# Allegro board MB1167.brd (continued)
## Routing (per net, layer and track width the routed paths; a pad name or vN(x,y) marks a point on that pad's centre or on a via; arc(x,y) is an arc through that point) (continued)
U5V_ST_LINK: length 36.3
  TOP w0.508: 35.83,58.04 C55.2 35.18,57.43 ; 36.22,57.53 U17.6 ; U17.7 34.95,57.02
  BOTTOM w1.016: 35.48,60.91 5.38,60.91 4.57,61.72 JP13.11
  vias: v1(36.2,60.07) v1(36.2,59.44)
USB_RENUMN: length 11
  TOP w0.127: U21.38 30.44,35.9 29.72,35.18 24.26,35.18 v1(22.35,33.27)
  BOTTOM w0.127: R294.2 v1(22.35,33.27)
VREF+: length 16.3
  TOP w0.381: v5(73.21,143.29) 73.61,142.89 U4.P1
  TOP w0.508: R33.2 v1(67.94,145.54)
  BOTTOM w0.381: C110.2 73.66,143.76 73.21,143.31 v5(73.21,143.29)
  BOTTOM w0.508: v5(73.21,143.29) 72.87,143.29 72.26,143.89 69.72,143.89 68.07,145.54 v1(67.94,145.54) 67.18,146.3 C105.1 66.55,149.22 67.18,149.86 TP6.1
VUSB_ST_LINK: length 77.1
  TOP w0.508: 30.78,50.16 C59.1 ; C59.1 32.72,50.16 ; C59.1 31.75,51 ; C59.1 31.75,49.33 ; U17.1 33.68,51.68 ; U17.1 34.16,50.59 ; U17.1 33.2,50.59 ; U17.1 33.68,49.5 ; 31.88,51.85 R156.1 ; R156.1 31.27,52.45 ; R156.1 32.49,52.45 ; R200.1 11.68,21.59 CN21.1 ; 34.95,49.5 U17.2 ; U17.2 34.47,50.59 ; U17.2 34.95,51.94 ; 26.2,74.93 D12.1 ; D12.1 26.82,75.54 ; D12.1 26.82,74.32 ; R159.1 35.2,49.07 ; R159.1 34.72,48.59 ; R159.1 35.2,48.11
  L4_SIG w1.016: 28.83,56.39 28.83,60.83 25.4,64.26 25.4,71.96 25.81,72.36 ; 28.83,52.73 28.83,45.87 18.24,35.28 18.24,33.81
  BOTTOM w0.508: 17.82,33.15 R293.2 18.41,33.76
  BOTTOM w1.016: CN21.1 14.35,24.26 14.35,31.75 15.95,33.35 16.51,33.35
  vias: v1(17.35,33.73) v1(17.37,33.02) v1(26.04,73.91) v1(26.67,73.91) v1(28.8,55.37) v1(28.8,54.66) v1(28.8,53.9)

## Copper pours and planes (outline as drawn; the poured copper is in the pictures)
+1V8 on TOP: 107.06,43.05 108.46,43.05 108.97,43.56 108.97,47.62 109.22,47.88 110.49,47.88 110.87,47.5 110.87,43.56 111.38,43.05 119.51,43.05 120.14,42.42 120.14,38.35 119.63,37.85 108.36,37.85 106.68,39.52 106.68,42.67
+1V8 on BOTTOM: 154.56,159.38 154.81,159.13 154.81,156.72 154.56,156.46 148.13,156.46 147.32,155.65 147.32,119.13 139.01,110.82 139.01,100.3 138.53,99.82 136.4,99.82 136.02,100.2 136.02,111.46 143.89,119.33 143.89,153.85 143.76,153.97 143.76,158.37 144.78,159.38
+1V8 on BOTTOM: 115.7,42.67 120.52,42.67 121.28,41.91 121.28,27.64 119.05,25.4 115.82,25.4 114.94,26.29 114.94,41.91
+1V8 on L4_SIG: 134.75,101.47 137.79,101.47 138.3,100.97 138.3,100.08 136.27,98.04 135.51,98.04 131.95,94.49 131.95,92.08 123.06,83.19 123.06,40.89 120.14,37.97 116.08,37.97 115.82,38.23 115.82,42.67 116.71,43.56 117.98,43.56 119.25,44.83 119.25,85.98
+2V8 on TOP: 140.08,156.59 140.46,156.21 140.46,151 140.21,150.75 131.06,150.75 130.43,151.38 130.43,155.32 131.83,156.72 131.83,160.53 131.95,160.66 133.6,160.66 133.73,160.53 133.73,157.23 134.37,156.59
+2V8 on L3_VCC: 136.76,137.16 134.87,139.04 134.87,156.1 137.27,158.5 156.34,158.5 156.34,148.34 156.34,148.33 156.34,146.18 156.21,146.05 153.03,146.05 152.15,145.16 152.15,137.77 151.53,137.16
+3V3 on TOP: 43.31,56.13 61.21,56.13 61.59,55.75 61.59,52.45 60.96,51.82 56.26,51.82 55.75,51.31 55.75,44.2 55.24,43.69 43.56,43.69 42.55,44.7 42.55,55.37
+3V3 on TOP: 106.3,48.51 108.2,48.51 108.46,48.26 108.46,44.7 108.2,44.45 106.3,44.45 106.05,44.7 106.05,48.26
+3V3 on L3_VCC: 0.51,0.51 0.51,13.93 29.55,13.93 31.33,15.72 31.33,26.01 31.97,26.65 40.54,26.65 42.5,28.61 42.5,40.06 41.02,41.54 26.76,41.54 24.07,44.24 24.07,69.76 22.46,71.36 0.51,71.36 0.51,82.03 2,82.03 2.39,82.43 2.39,83.5 2,83.9 0.51,83.9 0.51,86.78 2,86.78 2.39,87.18 2.39,88.25 2,88.65 0.51,88.65 0.51,96.39 2,96.39 2.39,96.78 2.39,97.86 2,98.25 0.51,98.25 0.51,101.14 2,101.14 2.39,101.53 2.39,102.61 2,103 0.51,103 0.51,106.93 5.95,106.93 6.6,107.59 6.6,111.1 5.95,111.76 3.41,111.76 3.3,111.87 3.3,113.69 3.41,113.79 5.19,113.79 6.35,114.96 6.35,116.1 6.96,116.71 7.34,116.71 8,117.37 8,118.85 7.6,119.25 0.51,119.25 0.51,172.21 156.34,172.21 156.34,159 137.05,159 134.37,156.32 134.37,138.83 136.55,136.65 151.74,136.65 152.65,137.56 152.65,144.91 153.29,145.54 155.96,145.54 156.34,145.16 156.34,52.91 155.69,47.08 156.34,41.24 156.34,0.51 ; 1 cut-out
+3V3_ST_LINK on L3_VCC: 0.51,14.44 0.51,70.86 22.25,70.86 23.56,69.55 23.56,44.03 26.55,41.03 40.81,41.03 42,39.85 42,28.82 40.33,27.16 31.76,27.16 30.83,26.22 30.83,15.93 29.34,14.44
+5V on TOP: 11.07,63.17 9.47,61.57 6.58,61.57 6.02,62.13 6.02,76.35 6.54,76.87 13.32,76.87 13.77,76.43 13.77,71.04 16.55,68.26 48.2,68.26 48.64,67.82 48.64,62.61 47.88,61.85 47.88,56.9 47.62,56.64 43.81,56.64 43.43,57.02 43.43,62.48 42.75,63.17
+5V on TOP: 130.68,157.48 128.78,157.48 128.27,157.99 128.27,162.23 128.47,162.43 130.86,162.43 131.06,162.23 131.06,157.86
+5V on BOTTOM: 13.84,92.15 12.09,92.15 11.68,92.56 11.68,97.97 16.59,102.87 16.59,115.16 17.22,115.8 21.01,115.8 21.21,115.6 21.21,114.17 19.91,112.88 19.91,102.57 14.05,96.7 14.05,92.35
+5V on L4_SIG: 130.07,161.59 128.57,161.59 128.32,161.85 128.32,167.94 125.93,170.33 115.44,170.33 110.39,165.28 109.65,165.28 107.92,167 71.27,167 69.9,168.38 30.23,168.38 28.92,167.07 28.92,156.53 28.57,156.18 28.57,149.61 19.3,140.34 19.3,118.24 20.93,116.61 20.95,116.61 21.36,116.2 21.36,113.51 21.03,113.18 17.5,113.18 12.19,118.49 12.19,142.56 25.34,155.7 25.34,168.16 28.42,171.25 113.42,171.25 114.16,171.98 127.91,171.98 130.33,169.57 130.33,161.85
+5V on L4_SIG: 8.66,97.46 13.21,97.46 13.74,96.93 13.74,72.75 12.62,71.63 6.38,71.63 6.05,71.96 6.05,76.63 10.64,81.23 10.64,94.36 10.19,94.82 8.81,94.82 8.51,95.12 8.51,97.31
D5V on TOP: 39.67,125.68 39.67,123.88 37.97,122.17 29.34,122.17 28.96,122.56 28.96,123.44 29.21,123.7 36.96,123.7 39.12,125.86 39.5,125.86
D5V on TOP: 42.93,125.91 44.22,125.91 44.58,125.55 44.58,121.62 45.06,121.13 45.06,120.7 44.88,120.52 43.97,120.52 43.64,120.85 43.64,122.58 43.66,122.61 43.66,124.69 43.31,125.04 43.03,125.04 42.93,125.15
D5V on TOP: 106.93,125.98 108.08,125.98 108.2,125.86 108.2,124.97 108.08,124.84 106.93,124.84 106.81,124.97 106.81,125.86
D5V on BOTTOM: 14.68,95.22 15.21,95.22 21.54,101.55 21.54,112.12 22.89,113.46 22.89,116.71 28.47,122.3 30.48,122.3 30.73,122.56 30.73,123.32 30.35,123.7 27.69,123.7 21.84,117.86 21.84,113.92 20.42,112.5 20.42,102.06 14.43,96.06 14.43,95.48
D5V on L4_SIG: 106.93,125.98 108.33,125.98 108.58,125.73 108.58,124.59 105.92,121.92 97.16,121.92 95,119.76 62.36,119.76 60.55,121.56 47.88,121.56 46.58,120.27 44.07,120.27 43.94,120.4 43.94,121.54 44.2,121.79 45.82,121.79 46.58,122.56 61.21,122.56 62.74,121.03 94.11,121.03 96.14,123.06 104.9,123.06 106.81,124.97 106.81,125.86
D5V on L4_SIG: 14.71,96.47 15.6,96.47 15.82,96.24 15.82,72.01 10.36,66.55 3.84,66.55 3.4,66.98 3.4,68.99 3.73,69.32 8.36,69.32 8.56,69.11 10.97,69.11 14.58,72.72 14.58,96.34
GND on BOTTOM (solid shape): 35.31,29.56 35.81,30.06 35.81,28.7 34.8,28.7 34.8,30.07
GND on TOP: 22.86,117.86 33.4,117.86 34.92,116.33 34.92,113.41 32.89,111.38 30.48,111.38 30.48,112.78 26.8,112.78 26.8,111.38 25.53,111.38 25.34,111.19 25.34,109.41 25.15,109.22 22.35,109.22 21.97,109.6 21.97,116.97
GND on TOP: 77.6,151.38 69.47,151.38 69.22,151.64 69.22,155.45 71.75,157.99 91.57,157.99 91.95,157.61 91.95,150.75 91.03,149.83 87.02,149.83 85.72,151.13 77.85,151.13
GND on TOP: 111.89,48.51 118.75,48.51 119,48.26 119,44.32 118.62,43.94 111.89,43.94 111.63,44.2 111.63,48.26
GND on TOP: 141.48,156.34 143.64,156.34 144.15,155.83 144.15,151.38 143.64,150.88 141.22,150.88 140.97,151.13 140.97,155.83
GND on TOP: 22.23,59.31 27,59.31 27.46,58.85 27.46,52.35 27.18,52.07 22.1,52.07 21.72,52.45 21.72,58.8
GND on TOP: 54.48,56.9 54.23,56.64 50.55,56.64 50.36,56.83 50.36,61.28 50.16,61.47 50.16,67.31 50.42,67.56 61.09,67.56 61.59,67.06 61.59,57.15 61.34,56.9
GND on TOP: 43.94,20.32 42.49,18.87 27.89,18.87 27.84,18.92 16.97,18.92 15.7,20.19 15.7,26.92 18.21,29.44 19.53,29.44 23.06,32.97 27.64,32.97 28.31,32.3 28.31,28.63 30.85,26.09 43.38,26.09 43.94,25.53
GND on TOP: 141.25,131.93 141.4,132.08 144.17,132.08 144.53,131.72 144.53,117.35 144.27,117.09 137.79,117.09 137.29,117.6 137.29,126.49 137.34,126.49 138.1,127.23 138.79,127.48 139.6,128.09 140,128.5 140.18,128.7 140.4,128.98 140.58,129.26 140.75,129.58 140.91,129.94 141.07,130.45 141.17,130.94 141.2,131.12
GND on BOTTOM: 29.18,25.98 41.86,25.98 42.82,25.02 42.82,19.86 42.19,19.23 28.96,19.23 28.5,19.68 28.5,25.3
GND on BOTTOM: 24.92,117.91 32.44,117.91 33.63,116.71 33.63,112.55 32.64,111.56 24.43,111.56 24.42,111.57 24.23,111.57 23.94,111.86 22.66,111.86 22.56,111.96 22.56,112.34 23.22,113 23.22,116.2
GND on L2_GND, L5_GND: 0.51,0.51 0.51,82.03 2,82.03 2.39,82.43 2.39,83.5 2,83.9 0.51,83.9 0.51,86.78 2,86.78 2.39,87.18 2.39,88.25 2,88.65 0.51,88.65 0.51,96.39 2,96.39 2.39,96.78 2.39,97.86 2,98.25 0.51,98.25 0.51,101.14 2,101.14 2.39,101.53 2.39,102.61 2,103 0.51,103 0.51,106.93 5.95,106.93 6.6,107.59 6.6,111.1 5.95,111.76 3.41,111.76 3.3,111.87 3.3,113.69 3.41,113.79 5.19,113.79 6.35,114.96 6.35,116.1 6.96,116.71 7.34,116.71 8,117.37 8,118.85 7.6,119.25 0.51,119.25 0.51,172.21 156.34,172.21 156.34,52.91 155.69,47.08 156.34,41.24 156.34,0.51
GND on L4_SIG: outline of 149 points within 0.56,0.64 156.34,117.6
GND on L4_SIG: 55.14,139.57 57.07,137.64 66.27,137.64 66.55,137.36 66.55,135.13 66.04,134.62 56.54,134.62 54.31,136.86 44.53,136.86 43.99,137.39 43.99,138.4 44.18,138.6 44.18,139.23 44.53,139.57
GND on L4_SIG: 41.15,106.3 48.39,106.3 49.91,104.78 49.91,82.17 65.28,66.8 91.95,66.8 93.6,65.15 93.6,61.98 89.62,58 87.72,58 85.75,56.03 85.75,54.13 76.23,44.6 75.13,44.6 73.23,42.7 56.82,42.7 55.52,41.4 51.69,41.4 48.11,37.82 34.29,37.82 33.77,38.34 33.77,61.35 29.72,65.41 29.72,93.42 39.5,103.2 39.5,104.65
GND on L4_SIG: 24.23,118.49 31.88,118.49 33.99,116.38 33.99,113.11 30.81,109.93 30.81,103.58 30.1,102.87 24.21,102.87 23.75,103.33 23.75,106.81 22.1,108.46 22.1,112.09 22.83,112.83 22.83,117.09
VBUS_FS2 on TOP (solid shape): 15.24,113.54 14.22,113.54 14.22,114.9 14.73,114.39 15.24,114.9
VDD_MCU on BOTTOM: 59.56,149.86 60.58,150.88 61.85,150.88 62.36,150.37 62.36,139.06 62.1,138.81 59.82,138.81 59.56,139.06
VDD_MCU on L3_VCC: 58.78,130.3 58.17,130.92 58.17,150.52 58.78,151.13 61.87,151.13 62.23,150.77 62.23,148.23 62.89,147.57 71.73,147.57 74.27,150.11 87.78,150.11 89.41,148.48 89.41,131.93 87.78,130.3
E5V on TOP: 20.83,52.7 20.83,58.8 20.32,59.31 7.11,59.31 5.72,60.71 5.72,65.79 5.21,66.29 1.27,66.29 1.02,66.04 1.02,54.74 1.4,54.36 12.19,54.36 14.29,52.26 20.38,52.26
MIC_CLK on BOTTOM (solid shape): 123.19,14.73 121.82,14.73 122.33,15.24 121.83,15.75 123.19,15.75
MIC_DATA on BOTTOM (solid shape): 129.67,14.73 128.75,14.73 128.24,15.24 128.75,15.75 129.67,15.75
NETC5_1 on TOP: 134.49,163.32 136.53,163.32 137.03,162.81 137.03,159.64 137.16,159.51 139.19,159.51 139.45,159.26 139.45,157.35 139.19,157.1 134.87,157.1 134.24,157.73 134.24,163.07
NETC6_2 on TOP (solid shape): 64.64,159.99 64.14,159.48 63.63,159.99 63.63,160.91 64.64,160.91
NETC6_2 on BOTTOM (solid shape): 40.86,145.79 41.37,145.29 40.01,145.29 40.01,146.3 41.37,146.3
NETC7_2 on TOP (solid shape): 70.99,160.12 70.48,159.61 69.98,160.12 69.98,161.04 70.99,161.04
NETC7_2 on BOTTOM (solid shape): 116.59,132.72 115.22,132.72 115.73,133.23 115.22,133.73 116.59,133.73
NETC8_2 on BOTTOM (solid shape): 48.13,150.24 46.77,150.24 47.28,150.75 46.77,151.26 48.13,151.26
NETC9_2 on BOTTOM (solid shape): 40.86,148.84 41.37,148.34 40.01,148.34 40.01,149.35 41.37,149.35
NETC10_2 on BOTTOM (solid shape): 109.57,130.81 110.07,130.3 108.71,130.3 108.71,131.32 110.08,131.32
NETC11_1 on BOTTOM (solid shape): 48.13,129.03 47.21,129.03 46.7,129.54 47.21,130.05 48.13,130.05
NETC12_2 on BOTTOM (solid shape): 48.13,137.29 47.21,137.29 46.7,137.79 47.21,138.3 48.13,138.3
NETC13_2 on BOTTOM (solid shape): 41.43,141.6 40.93,141.1 40.01,141.1 40.01,142.11 40.93,142.11
NETC14_2 on BOTTOM (solid shape): 48.13,147.07 47.21,147.07 46.7,147.57 47.21,148.08 48.13,148.08
NETC15_1 on BOTTOM (solid shape): 41.43,139.83 40.93,139.32 40.01,139.32 40.01,140.34 40.93,140.34
NETC17_1 on TOP (solid shape): 64.64,158.37 63.63,158.37 63.63,159.73 64.13,159.22 64.64,159.73
NETC18_2 on TOP (solid shape): 70.99,158.5 69.98,158.5 69.98,159.86 70.48,159.35 70.99,159.86
NETC18_2 on BOTTOM (solid shape): 116.59,126.49 115.22,126.49 115.73,127 115.22,127.51 116.59,127.51
NETC34_1 on TOP: 0.89,107.57 0.51,107.95 0.51,109.6 0.64,109.73 2.03,109.73 2.41,110.11 2.41,111.51 2.16,111.76 0.76,111.76 0.53,111.99 0.53,114.5 0.58,114.55 0.64,114.55 0.68,114.6 2,114.6 2.39,115 2.39,116.07 2,116.47 0.76,116.47 0.64,116.59 0.64,118.75 5.72,118.75 5.84,118.87 7.24,118.87 7.49,118.62 7.49,117.6 7.11,117.22 6.73,117.22 5.84,116.33 5.84,114.94 5.08,114.17 3.3,114.17 3.05,113.92 3.05,111.76 3.43,111.38 5.59,111.38 6.22,110.74 6.22,107.82 5.97,107.57
NETC34_1 on L2_GND, L3_VCC, L5_GND: 0.51,107.44 0.51,109.85 2,109.85 2.39,110.25 2.39,111.32 2,111.72 0.51,111.72 0.51,114.6 2,114.6 2.39,115 2.39,116.07 2,116.47 0.51,116.47 0.51,118.75 7.39,118.75 7.49,118.64 7.49,117.58 7.13,117.22 6.75,117.22 5.84,116.31 5.84,115.17 4.97,114.3 3.2,114.3 2.79,113.9 2.79,111.65 3.2,111.25 5.74,111.25 6.1,110.89 6.1,107.8 5.74,107.44
NETC36_1 on TOP (solid shape): 15.24,115.16 14.73,114.65 14.22,115.16 14.22,116.08 15.24,116.08
NETC36_1 on TOP (solid shape): 11.94,114.72 11.43,115.22 10.92,114.71 10.92,116.08 11.94,116.08
NETC60_1 on TOP: 23.11,50.42 23.5,50.04 23.5,42.29 23.11,41.91 20.57,41.91 20.32,42.16 20.32,50.16 20.57,50.42
NETC60_2 on TOP: 9.65,33.15 3.18,33.15 2.29,34.04 2.29,43.94 7.37,49.02 7.37,49.91 9.02,51.56 10.8,51.56 12.7,49.66 19.43,49.66 19.81,49.28 19.81,41.91 19.56,41.66 14.22,41.66 12.7,43.18 9.14,43.18 8.38,42.42 8.38,37.08 10.03,35.43 10.03,33.53
NETC62_1 on TOP: 65.15,39.5 66.93,39.5 67.06,39.37 67.06,34.16 66.17,33.27 65.41,33.27 64.9,33.78 64.9,39.24
NETC62_2 on TOP: 61.98,39.5 63.88,39.5 64.26,39.12 64.26,33.66 64.68,33.24 64.68,32.85 64.77,32.77 64.77,30.1 64.52,29.84 62.1,29.84 61.59,30.35 61.59,39.12
NETC137_2 on L4_SIG: 131.19,126.36 131.57,125.98 131.57,116.46 130.94,115.82 127.25,115.82 127,116.08 127,125.98 127.38,126.36
NETCN1_3 on BOTTOM (solid shape): 116.59,121.92 115.67,121.92 115.16,122.43 115.67,122.94 116.59,122.94
NETCN1_5 on BOTTOM (solid shape): 48.13,144.02 46.77,144.02 47.28,144.53 46.77,145.03 48.13,145.03
NETCN1_9 on BOTTOM (solid shape): 48.01,123.7 46.64,123.7 47.15,124.21 46.64,124.71 48.01,124.71
NETCN1_11 on BOTTOM (solid shape): 111.25,124.97 110.33,124.97 109.82,125.48 110.33,125.98 111.25,125.98
NETCN1_13 on BOTTOM (solid shape): 48.13,140.34 46.77,140.34 47.28,140.85 46.77,141.35 48.13,141.35
NETCN1_21 on BOTTOM (solid shape): 110.14,135.76 109.63,135.25 108.71,135.25 108.71,136.27 109.63,136.27
NETCN1_23 on BOTTOM (solid shape): 110.14,138.56 109.63,138.05 108.71,138.05 108.71,139.06 109.63,139.06
NETCN4_33 on TOP (solid shape): 109.47,159.29 108.97,159.8 108.46,159.29 108.46,160.66 109.47,160.66
NETCN5_3 on BOTTOM (solid shape): 77.47,149.83 76.96,149.32 76.45,149.83 76.45,150.75 77.47,150.75
NETCN5_6 on BOTTOM (solid shape): 74.3,149.83 73.79,149.32 73.28,149.83 73.28,150.75 74.3,150.75
NETCN6_3 on BOTTOM (solid shape): 80.77,149.83 80.26,149.32 79.76,149.83 79.76,150.75 80.77,150.75
NETCN6_4 on BOTTOM (solid shape): 84.45,149.83 83.95,149.32 83.44,149.83 83.44,150.75 84.45,150.75
NETCN12_12 on TOP (solid shape): 91.57,140.34 90.21,140.34 90.71,140.84 90.2,141.35 91.57,141.35
NETCN12_14 on TOP (solid shape): 95.5,140.34 94.14,140.34 94.65,140.84 94.14,141.35 95.5,141.35
NETCN12_16 on TOP (solid shape): 95.5,144.15 94.14,144.15 94.65,144.65 94.14,145.16 95.5,145.16
NETCN12_18 on TOP (solid shape): 90.17,147.99 89.66,148.5 89.15,147.99 89.15,149.35 90.17,149.35
NETCN12_20 on TOP (solid shape): 128.52,99.57 127.51,99.57 127.51,100.93 128.01,100.42 128.52,100.93
NETCN14_4 on BOTTOM (solid shape): 40.99,130.68 41.49,130.18 40.13,130.18 40.13,131.19 41.5,131.19
NETCN16_3 on BOTTOM (solid shape): 109.57,119.63 110.07,119.13 108.71,119.13 108.71,120.14 110.08,120.14
NETCN16_7 on BOTTOM (solid shape): 111.25,123.44 110.33,123.44 109.82,123.95 110.33,124.46 111.25,124.46
NETCN17_1 on TOP: 9.4,42.29 12.7,42.29 14.22,40.77 21.21,40.77 21.72,40.26 21.72,37.21 21.21,36.7 9.78,36.7 9.02,37.47 9.02,41.91
NETCN20_43 on BOTTOM (solid shape): 116.59,123.44 115.22,123.44 115.73,123.95 115.22,124.46 116.59,124.46
NETD5_C3 on BOTTOM (solid shape): 116.59,129.67 115.22,129.67 115.73,130.18 115.22,130.68 116.59,130.68
NETJP6_3 on BOTTOM (solid shape): 116.59,124.97 115.22,124.97 115.73,125.48 115.22,125.98 116.59,125.98
NETJP20_2 on BOTTOM (solid shape): 109.57,129.28 110.07,128.78 108.71,128.78 108.71,129.79 110.08,129.79
NETJP21_2 on BOTTOM (solid shape): 40.86,150.49 41.37,149.99 40.01,149.99 40.01,151 41.37,151
NETJP21_3 on TOP (solid shape): 78.49,121.95 78.49,121.03 77.47,121.03 77.47,121.95 77.98,122.46
NETJP22_2 on BOTTOM (solid shape): 48.13,145.54 47.21,145.54 46.7,146.05 47.21,146.56 48.13,146.56
NETJP22_3 on TOP (solid shape): 78.49,125.63 78.49,124.71 77.47,124.71 77.47,125.63 77.98,126.14
NETL2_1 on TOP (solid shape): 11.94,114.46 11.94,113.54 10.92,113.54 10.92,114.46 11.43,114.97
NETLD8_2 on TOP: 11.3,93.98 12.07,93.98 12.19,93.85 12.19,91.95 11.94,91.69 11.94,89.41 11.68,89.15 8.64,89.15 8.38,89.41 8.38,91.82 9.02,92.46 11.05,92.46 11.18,92.58 11.18,93.85
NETR31_1 on TOP (solid shape): 90.17,147.73 90.17,146.81 89.15,146.81 89.15,147.73 89.66,148.24
NETR31_1 on TOP (solid shape): 91.69,147.73 91.69,146.81 90.68,146.81 90.68,147.73 91.19,148.24
NETR34_1 on TOP (solid shape): 128.52,101.19 128.02,100.68 127.51,101.19 127.51,102.11 128.52,102.11
NETR34_1 on TOP (solid shape): 130.05,103.54 130.05,102.62 129.03,102.62 129.03,103.54 129.54,104.04
NETR34_1 on TOP (solid shape): 130.05,101.19 129.54,100.68 129.03,101.19 129.03,102.11 130.05,102.11
NETR35_1 on TOP (solid shape): 94.39,144.65 93.88,144.15 92.96,144.15 92.96,145.16 93.88,145.16
NETR37_1 on TOP (solid shape): 94.39,140.84 93.88,140.34 92.96,140.34 92.96,141.35 93.88,141.35
NETR39_1 on TOP (solid shape): 90.46,140.84 89.95,140.34 89.03,140.34 89.03,141.35 89.95,141.35
NETR46_2 on BOTTOM (solid shape): 116.84,136.93 115.92,136.93 115.41,137.44 115.92,137.95 116.84,137.95
NETR47_2 on BOTTOM (solid shape): 48.13,127.51 47.21,127.51 46.7,128.02 47.21,128.52 48.13,128.52
NETR48_2 on BOTTOM (solid shape): 41.43,138.3 40.93,137.79 40.01,137.79 40.01,138.81 40.93,138.81
NETR49_2 on BOTTOM (solid shape): 48.13,142.49 46.77,142.49 47.28,143 46.77,143.51 48.13,143.51
NETR50_2 on BOTTOM (solid shape): 48.13,148.72 46.77,148.72 47.28,149.23 46.77,149.73 48.13,149.73
NETR62_2 on BOTTOM (solid shape): 48.13,138.81 47.21,138.81 46.7,139.32 47.21,139.83 48.13,139.83
NETR94_2 on TOP (solid shape): 18.16,109.95 17.65,109.44 17.14,109.95 17.14,110.87 18.16,110.87
NETR94_2 on TOP (solid shape): 21.08,109.95 20.57,109.44 20.07,109.95 20.07,110.87 21.08,110.87
NETR129_2 on TOP: 10.92,97.79 13.84,97.79 13.97,97.66 13.97,94.74 13.84,94.61 10.92,94.61 10.67,94.87 10.67,97.54
NETR248_2 on TOP (solid shape): 90.01,137.92 90.52,137.41 89.15,137.41 89.15,138.43 90.52,138.43
NETR251_2 on BOTTOM (solid shape): 65.15,135 63.79,135 64.3,135.51 63.79,136.02 65.15,136.02
NETSB9_2 on TOP (solid shape): 91.69,137.41 90.77,137.41 90.27,137.92 90.77,138.43 91.69,138.43
NETSB14_1 on TOP (solid shape): 18.16,108.33 17.14,108.33 17.14,109.69 17.65,109.19 18.16,109.7
NETSB15_1 on TOP (solid shape): 21.08,108.33 20.07,108.33 20.07,109.69 20.57,109.19 21.08,109.7
NETSB18_1 on TOP (solid shape): 130.05,99.57 129.03,99.57 129.03,100.93 129.54,100.42 130.05,100.93
NETSB20_2 on BOTTOM (solid shape): 122.08,15.24 121.57,14.73 120.65,14.73 120.65,15.75 121.57,15.75
NETSB21_1 on BOTTOM (solid shape): 127.98,15.24 128.49,14.73 127.13,14.73 127.13,15.75 128.49,15.75
NETSB32_1 on BOTTOM (solid shape): 40.86,147.32 41.37,146.81 40.01,146.81 40.01,147.83 41.37,147.83
NETSB36_1 on BOTTOM (solid shape): 40.86,144.27 41.37,143.76 40.01,143.76 40.01,144.78 41.37,144.78
NETSB47_2 on BOTTOM (solid shape): 64.04,135.51 63.53,135 62.61,135 62.61,136.02 63.53,136.02
NETSB49_1 on BOTTOM (solid shape): 116.59,131.19 115.22,131.19 115.73,131.7 115.22,132.21 116.59,132.21
PA0 on BOTTOM (solid shape): 42.55,146.81 41.62,146.81 41.12,147.32 41.62,147.83 42.55,147.83
PA0 on BOTTOM (solid shape): 42.55,145.29 41.62,145.29 41.12,145.8 41.62,146.3 42.55,146.3
PA0 on BOTTOM (solid shape): 42.55,143.76 41.62,143.76 41.12,144.27 41.62,144.78 42.55,144.78
PA1 on BOTTOM (solid shape): 47.02,150.75 46.51,150.24 45.59,150.24 45.59,151.26 46.51,151.26
PA1 on BOTTOM (solid shape): 47.02,149.22 46.51,148.72 45.59,148.72 45.59,149.73 46.51,149.73
PA2 on BOTTOM (solid shape): 42.55,149.99 41.62,149.99 41.12,150.5 41.62,151 42.55,151
PA2 on BOTTOM (solid shape): 42.55,148.34 41.62,148.34 41.12,148.84 41.62,149.35 42.55,149.35
PA6 on TOP (solid shape): 109.47,159.04 109.47,158.12 108.46,158.12 108.46,159.04 108.97,159.54
PA7 on BOTTOM (solid shape): 47.02,144.53 46.51,144.02 45.59,144.02 45.59,145.03 46.51,145.03
PA7 on BOTTOM (solid shape): 47.02,143 46.51,142.49 45.59,142.49 45.59,143.51 46.51,143.51
PA8 on BOTTOM (solid shape): 115.47,127 114.97,126.49 114.05,126.49 114.05,127.51 114.97,127.51
PA8 on BOTTOM (solid shape): 115.47,125.48 114.97,124.97 114.05,124.97 114.05,125.98 114.97,125.98
PA8 on BOTTOM (solid shape): 115.47,123.95 114.97,123.44 114.05,123.44 114.05,124.46 114.97,124.46
PA9 on BOTTOM (solid shape): 111.25,128.78 110.33,128.78 109.82,129.29 110.33,129.79 111.25,129.79
PA11 on BOTTOM (solid shape): 111.25,130.3 110.33,130.3 109.82,130.81 110.33,131.32 111.25,131.32
PA12 on BOTTOM (solid shape): 115.47,133.22 114.97,132.72 114.05,132.72 114.05,133.73 114.97,133.73
PA12 on BOTTOM (solid shape): 115.47,131.7 114.97,131.19 114.05,131.19 114.05,132.21 114.97,132.21
PA12 on BOTTOM (solid shape): 115.47,130.18 114.97,129.67 114.05,129.67 114.05,130.68 114.97,130.68
PAR_D0 on BOTTOM (solid shape): 114.9,122.43 115.41,121.92 114.05,121.92 114.05,122.94 115.41,122.94
PAR_D2 on BOTTOM (solid shape): 109.57,125.47 110.07,124.97 108.71,124.97 108.71,125.98 110.08,125.98
PAR_D2 on BOTTOM (solid shape): 109.57,123.95 110.07,123.44 108.71,123.44 108.71,124.46 110.08,124.46
PAR_D6 on TOP (solid shape): 91.69,147.99 91.19,148.5 90.68,147.99 90.68,149.35 91.69,149.35
PAR_D7 on TOP (solid shape): 130.05,103.79 129.54,104.3 129.03,103.79 129.03,105.16 130.05,105.16
PAR_D11 on BOTTOM (solid shape): 111.25,119.13 110.33,119.13 109.82,119.63 110.33,120.14 111.25,120.14
PB0 on BOTTOM (solid shape): 46.89,124.21 46.39,123.7 45.47,123.7 45.47,124.71 46.39,124.71
PB1 on BOTTOM (solid shape): 47.02,140.84 46.51,140.34 45.59,140.34 45.59,141.35 46.51,141.35
PB12 on BOTTOM (solid shape): 42.67,130.18 41.75,130.18 41.24,130.68 41.75,131.19 42.67,131.19
PC1 on BOTTOM (solid shape): 46.45,147.57 46.95,147.07 45.59,147.07 45.59,148.08 46.96,148.08
PC1 on BOTTOM (solid shape): 46.45,146.05 46.95,145.54 45.59,145.54 45.59,146.56 46.96,146.56
PC2 on BOTTOM (solid shape): 42.55,141.1 41.18,141.1 41.69,141.61 41.18,142.11 42.55,142.11
PC3 on BOTTOM (solid shape): 46.45,139.32 46.95,138.81 45.59,138.81 45.59,139.83 46.96,139.83
PC3 on BOTTOM (solid shape): 46.45,137.79 46.95,137.29 45.59,137.29 45.59,138.3 46.96,138.3
PC4 on BOTTOM (solid shape): 42.55,139.32 41.18,139.32 41.69,139.83 41.18,140.34 42.55,140.34
PC4 on BOTTOM (solid shape): 42.55,137.79 41.18,137.79 41.69,138.31 41.18,138.81 42.55,138.81
PC5 on BOTTOM (solid shape): 46.45,129.54 46.95,129.03 45.59,129.03 45.59,130.05 46.96,130.05
PC5 on BOTTOM (solid shape): 46.45,128.01 46.95,127.51 45.59,127.51 45.59,128.52 46.96,128.52
PC14 on BOTTOM (solid shape): 83.95,149.06 84.45,149.57 84.45,148.21 83.44,148.21 83.44,149.57
PC15 on BOTTOM (solid shape): 80.27,149.06 80.77,149.57 80.77,148.21 79.76,148.21 79.76,149.57
PG6 on TOP (solid shape): 78.49,122.21 77.98,122.72 77.47,122.21 77.47,123.57 78.49,123.57
PG7 on TOP (solid shape): 78.49,125.89 77.98,126.4 77.47,125.89 77.47,127.25 78.49,127.25
PG11 on BOTTOM (solid shape): 111.25,135.25 109.89,135.25 110.4,135.77 109.89,136.27 111.25,136.27
PH0 on BOTTOM (solid shape): 76.96,149.06 77.47,149.57 77.47,148.21 76.45,148.21 76.45,149.57
PH1 on BOTTOM (solid shape): 73.79,149.06 74.3,149.57 74.3,148.21 73.28,148.21 73.28,149.57
PH6 on BOTTOM (solid shape): 111.25,138.05 109.89,138.05 110.4,138.56 109.89,139.06 111.25,139.06
PH6 on BOTTOM (solid shape): 115.16,137.44 115.66,136.93 114.3,136.93 114.3,137.95 115.67,137.95
STM_RST on BOTTOM (solid shape): 35.81,30.32 35.31,29.81 34.8,30.32 34.8,31.24 35.81,31.24
U5V_ST_LINK on TOP (solid shape): 35.69,59.05 34.77,59.05 34.26,59.56 34.77,60.07 35.69,60.07
U5V_ST_LINK on TOP: 35.18,60.45 36.58,60.45 36.7,60.33 36.7,57.15 36.58,57.02 34.92,57.02 34.8,57.15 34.8,60.07
U5V_ST_LINK on BOTTOM: 36.7,59.18 36.58,59.05 35.56,59.05 35.31,59.31 35.31,61.34 35.43,61.47 36.58,61.47 36.7,61.34
VUSB_ST_LINK on TOP (solid shape): 34,59.57 34.51,59.05 33.15,59.05 33.15,60.07 34.51,60.07
VUSB_ST_LINK on L4_SIG (solid shape): 29.34,56.87 29.34,52.6 29.21,52.48 28.35,52.48 28.22,52.6 28.22,56.87 28.47,57.12 29.08,57.12
VUSB_ST_LINK on TOP: 25.65,75.82 26.92,75.82 27.3,75.44 27.3,74.17 26.67,73.53 25.78,73.53 25.65,73.66
VUSB_ST_LINK on TOP: 35.05,52.96 35.46,52.55 35.46,48.08 35.33,47.96 34.19,47.96 33.25,48.9 28.83,48.9 28.19,49.53 28.19,60.07 28.7,60.58 33.66,60.58 33.78,60.45 33.78,59.18 33.66,59.05 30.35,59.05 29.97,58.67 29.97,53.59 30.61,52.96
VUSB_ST_LINK on BOTTOM: 16.26,32.69 16.08,32.87 16.08,34.21 16.23,34.37 18.77,34.37 18.95,34.19 18.95,32.79 18.85,32.69
VUSB_ST_LINK on L4_SIG: 18.75,32.66 18.57,32.49 16.56,32.49 16.36,32.69 16.36,34.19 16.54,34.37 18.57,34.37 18.75,34.19
VUSB_ST_LINK on L4_SIG: 26.8,74.3 26.92,74.17 26.92,72.77 26.29,72.14 25.53,72.14 25.27,72.39 25.27,74.17 25.4,74.3

Small or netless copper shapes (teardrops, artwork), in the pictures only: 8 on TOP

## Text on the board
Ref Des/Silkscreen Bottom: STLINK | MFX | Rev.B | B | MB1167
Ref Des/Silkscreen Top: USART1_RX | USART1_TX | STlk | OTG_FS1 | power source | ST-LINK/V2-1 | OTG_FS2 | FS1 | FS2 | D5V | PSU | HS | Coupon | USART1 | PSU DC5V | OVER CURRENT | IrDA_RX | +5V | COM | AIN | RS232_RX | STLINK | ADC channel | RF E2P | +3V3 | PWR_EXT | GND | RESET# | PF10 | PB10 | PB14 | PH6 | PB12 | PB13 | PJ9 | PG7 | PG6 | PJ7 | PJ10 | PJ8 | PC4 | PC3 | PB2 | PJ3 | PF6 | PC0 | PA2 | PA0 | PA4 | PC2 | PF8 | PH0 | 0= | 1= | Flash | Sys mem | VBAT | 3V3 | POT | LD1 | MFX | TX | RX | PH3 | PF13 | PF12 | PG1 | PE7 | PE10 | PE12 | PE15 | PE13 | PD11 | PD12 | PG5 | PH11 | PD13 | PG2 | PD8 | PD9 | PD14 | 0 <--> 1 | PI11 | PB5 | PH1 | PF7 | PF9 | PA1 | PC1 | PA3 | PA6 | PA7 | PA5 | PB1 | PH4 | PI14 | PJ4 | PB11 | PB15 | PH7 | PJ5 | PJ6 | PC5 | PB0 | PJ0 | PJ2 | PJ1 | 5V | VDD_MCU | CON | PH5 | PF14 | PG0 | PF11 | PE9 | PE8 | PE11 | PF15 | PE14 | PH8 | PH10 | PH9 | PG4 | PH12 | PG3 | PD10 | PD15 | PG8 | VDDA | VREF+ | Motor Control | DATA | NOR_WP | CLK | NWAIT | PE4 | PE3 | PI5 | PI4 | PG15 | PI10 | PE1 | PE0 | PG10 | PD0 | PI2 | PI1 | PI0 | PH13 | TDO | PF5 | PF4 | PF3 | PE6 | BL_BOOT0 | Ethernet | I2S | PG12 | PG9 | PB7 | PD3 | PG13 | PJ12 | PG14 | PB8 | PG11 | PJ11 | PK0 | PA11 | PA9 | PB3 | PD6 | PC8 | PC11 | PC10 | PD2 | PC15 | PI15 | PI12 | PI8 | PK6 | PK4 | LD3 | PH15 | PH14 | PH2 | PE5 | PF2 | PF1 | PF0 | PE2 | PI7 | PI9 | PI6 | PD7 | PD5 | PD4 | PD1 | PI3 | Audio | CAMERA | TRACE | V_FS1 | PI13 | PC14 | PC13 | PK7 | PK5 | PB9 | PK3 | PB6 | PJ14 | PJ15 | PB4 | PJ13 | PC12 | PA15 | PK1 | PA14 | PK2 | PA13 | PA12 | PA10 | PC9 | PA8 | PC7 | PC6 | +2V8 | IrDA | CAN terminal | +1V8 | 25MHz | Crystal | MCO | Camera | CAN | JTAG | uSD | OTG | -HS | BL_RST | MICBIAS | SPDIF_IN | CAN_RX | CAN_RS | Audio_out2 | Audio_out1 | ETH_CLK | S | B | Reset | Wakeup/ | Tamper | Joystick | MB1167 Rev.B | STM32746G-EVAL
User.23: 1 | 3 | 5.1 | 6.1 | 8.9 | 9.9 | N/A | 90 OHM | 100 OHM | +/-10%
User.32: CN8 | CN1 | B1 | U4 | B2 | CN16 | CN3 | CN10 | CN4 | CN14_1 | U21 | CN5 | CN11 | RV2 | U10 | U27 | U7 | CN12 | U5 | CN14 | CN9 | CN13 | CN7 | CN23 | 1 | 845.00 | 545.00 | ST-Link | MB1063 | 0.00 | MB1043 | Designator5 | 400.00 | SDRAM | Speaker connector | Designator6 | Ethernet | Memory connector | Memory Connector | 118.36427 (mm)
User.41: FIGURE | SIZE | 6.0 | 8.0 | 10.0 | 12.0 | 30.0 | 32.0 | 38.0 | 40.0 | 48.0 | 53.0 | 64.0 | 95.0 | 126.0 | 177.0 | 28.0 | 33.46 | 39.0 | 47.0 | 58.0 | 67.0 | 77.0 | 79.0 | 125.0 | 138.0 | 33.0x30.0 | 59.0x33.0 | 126.0x40.0 | 140.0x50.0 | TOLERANCE | +3.0/-3.0 | +2.0/-2.0 | +5.0/-5.0 | DRILL CHART: TOP to BOTTOM | ALL UNITS ARE IN MILS | PLATED | NON-PLATED | ROTATION | - | 0.000 | 90.000 | QTY | 13 | 295 | 703 | 598 | 9 | 3 | 18 | 157 | 27 | 6 | 4 | 2 | 1 | 11 | 8 | 1907 | TOTAL HOLES:
